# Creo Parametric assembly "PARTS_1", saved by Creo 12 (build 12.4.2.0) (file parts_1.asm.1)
Units: Custom; MM, KILOGRAM, SECS

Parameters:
  PTC_WM_ITERATION = "0"
  PTC_WM_VERSION = "-.0"
  PTC_WM_LIFECYCLE_STATE = "In Work"
  PTC_WM_LIFECYCLE = "MO_CADDocument"
  PTC_WM_CREATED_BY = "Maximilian Roepper (Z0017RMS: MO)"
  PTC_WM_CREATED_ON = "18-Sep-26 11:36:42 AM"
  PTC_WM_MODIFIED_BY = "Maximilian Roepper (Z0017RMS: MO)"
  PTC_WM_MODIFIED_ON = "18-Sep-26 11:36:46 AM"
  PDMLINKNUMBER = "PDM000071455112"
  PTC_WM_NUMBER = "PDM000071455112"

Other parameters: WEIGHT, WEIGHT_FACTOR, WEIGHT_ADD, MC_ERRORS, SUPPLIER

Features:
  1. coordinate system
  2. imported feature
  3. component "TSSOP16_010_1"
  4. component "SMD_RESISTOR001_1"
  5. component "SMD_RESISTOR002_1"
  6. component "SMD_RESISTOR003_1"
  7. component "SMD_RESISTOR004_1"
  8. component "SMD_RESISTOR005_1"
  9. component "SMD_RESISTOR006_1"
  10. component "SMD_CAP001_1"
  11. component "SMD_CAP002_1"
  12. component "SOT23_1"
  13. component "SOT23-1_1"

Other named items: DRW_VIEW_ORG, ROUGH-GROB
